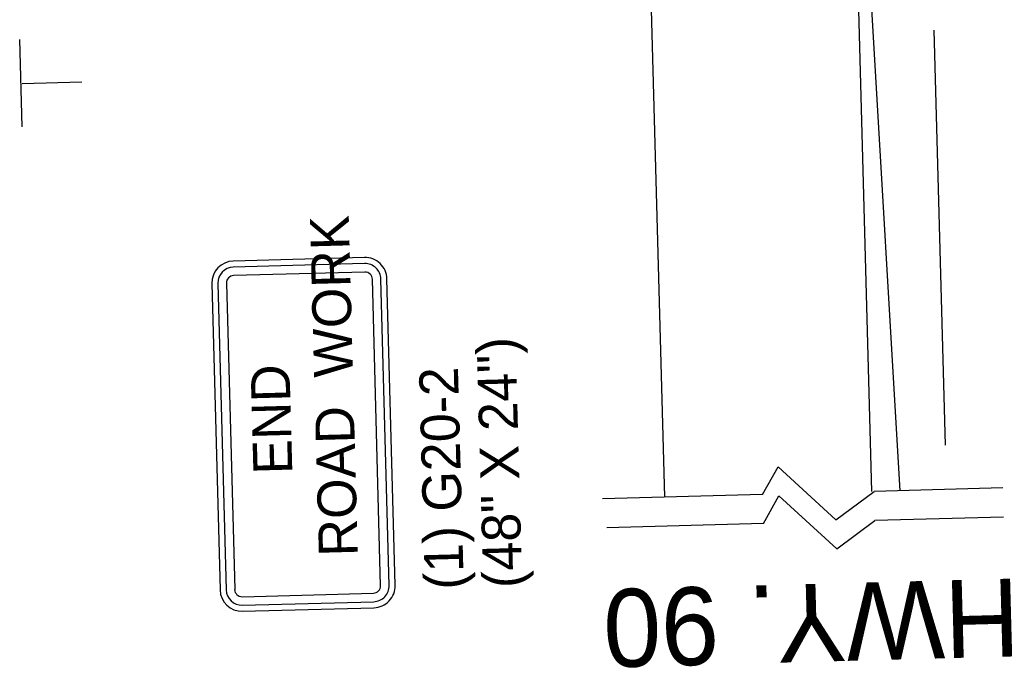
# Model space of a CAD drawing. Extents: x 1929653 to 1931621, y 596452 to 600944.
# Drawn here: x 1929711 to 1929940.4, y 597816.9 to 597966.8 of the extents above; entities that cross this region are included whole.
import ezdxf

# ---------------------------------------------------------------- set-up
doc = ezdxf.new("R2010")
doc.units = 0
for name, color, linetype in [('P_TC_Signs_Temporary', 7, 'Continuous'), ('R_Border', 7, 'Continuous'), ('R_Draft', 7, 'Continuous')]:
    doc.layers.add(name, color=color, linetype=linetype)

msp = doc.modelspace()

# ---------------------------------------------------------------- linework, layer by layer
at = {"layer": 'P_TC_Signs_Temporary'}
for p, q in [((1929790.71, 597911.85), (1929760.34, 597911.03)), ((1929790.75, 597910.44), (1929760.38, 597909.63)), ((1929790.8, 597908.47), (1929760.44, 597907.66)), ((1929755.42, 597905.83), (1929757.32, 597834.99)), ((1929756.83, 597905.87), (1929758.73, 597835.02)), ((1929758.79, 597905.93), (1929760.7, 597835.08)), ((1929794.43, 597835.98), (1929792.53, 597906.83)), ((1929796.4, 597836.03), (1929794.5, 597906.88)), ((1929797.81, 597836.07), (1929795.91, 597906.92)), ((1929762.43, 597833.43), (1929792.79, 597834.25)), ((1929762.48, 597831.47), (1929792.84, 597832.28)), ((1929762.52, 597830.06), (1929792.88, 597830.88))]:
    msp.add_line(p, q, dxfattribs=at)
for centre, radius, start, end in [((1929760.48, 597905.97), 5.06, 91.5377, 181.5377), ((1929790.84, 597906.79), 5.06, 1.5377, 91.5377), ((1929790.84, 597906.79), 3.66, 1.5377, 91.5377), ((1929760.48, 597905.97), 3.66, 91.5377, 181.5377), ((1929790.84, 597906.79), 1.69, 1.5377, 91.5377), ((1929760.48, 597905.97), 1.69, 91.5377, 181.5377), ((1929762.38, 597835.12), 5.06, 181.5377, 271.5377), ((1929762.38, 597835.12), 3.66, 181.5377, 271.5377), ((1929762.38, 597835.12), 1.69, 181.5377, 271.5377), ((1929792.75, 597835.94), 1.69, 271.5377, 1.5377), ((1929792.75, 597835.94), 3.66, 271.5377, 1.5377), ((1929792.75, 597835.94), 5.06, 271.5377, 1.5377)]:
    msp.add_arc(centre, radius, start, end, dxfattribs=at)
at = {"layer": 'R_Draft'}
for p, q in [((1929860.13, 597856.47), (1929835.62, 598755.2)), ((1929907.99, 597857.75), (1929883.87, 598756.49)), ((1929914.54, 597857.93), (1929894.83, 598195.36)), ((1929925.02, 597868.46), (1929922.44, 597964.39)), ((1929711.57, 597942.06), (1929711.03, 597962.26)), ((1929711.59, 597952.12), (1929725.37, 597952.49)), ((1929938.27, 597858.57), (1929908.54, 597857.77)), ((1929882.75, 597857.07), (1929845.76, 597856.08)), ((1929938.45, 597851.82), (1929908.72, 597851.02)), ((1929882.93, 597850.33), (1929846.76, 597849.36))]:
    msp.add_line(p, q, dxfattribs=at)
for points in [[(1929882.75, 597857.07), (1929886.34, 597863.49), (1929899.72, 597851.21), (1929908.54, 597857.77)], [(1929882.93, 597850.33), (1929886.52, 597856.74), (1929899.9, 597844.47), (1929908.72, 597851.02)]]:
    msp.add_lwpolyline(points, dxfattribs=at)

# ---------------------------------------------------------------- texts
at = {"layer": 'P_TC_Signs_Temporary'}
for s, p in [('ROAD  WORK', (1929789.18, 597842.84)), ('END', (1929774.04, 597861.84))]:
    msp.add_text(s, height=9, rotation=91.5377, dxfattribs=at).set_placement(p)
at = {"layer": 'R_Border'}
for s, height, rotation, p in [('(48" X 24")', 9, 91.5377, (1929827.18, 597835.53)), ('(1) G20-2', 9, 91.5377, (1929813.69, 597835.17)), ('HWY. 90', 18, 181.5377, (1929941.94, 597837.66))]:
    msp.add_text(s, height=height, rotation=rotation, dxfattribs=at).set_placement(p)

doc.saveas('drawing.dxf')
